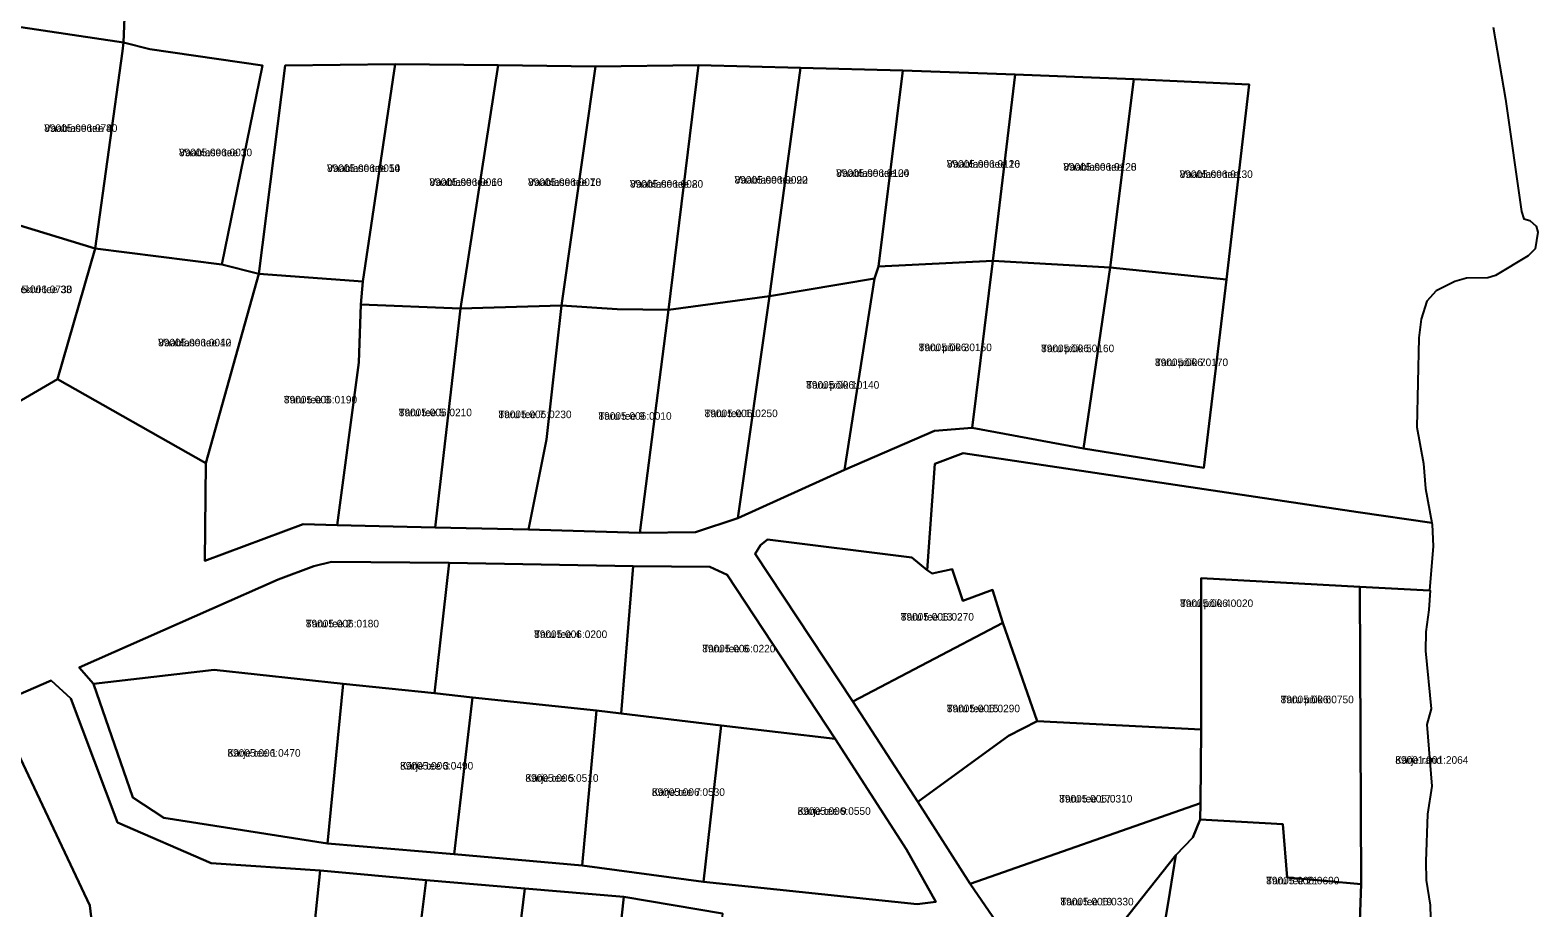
# Model space of a CAD drawing. Extents: x 526849 to 562296, y 6591741 to 6618546.
# Drawn here: x 551338.6 to 551637.5, y 6597493.2 to 6597667.2 of the extents above; entities that cross this region are included whole.
import ezdxf

# ---------------------------------------------------------------- set-up
doc = ezdxf.new("R2010")
doc.units = 0
for name, color, linetype in [('L_AADRESS', 7, 'Continuous'), ('PIIR', 7, 'Continuous'), ('TUNNUS', 7, 'Continuous')]:
    doc.layers.add(name, color=color, linetype=linetype)

msp = doc.modelspace()

# ---------------------------------------------------------------- linework, layer by layer
at = {"layer": 'PIIR'}
for points in [[(550642.16, 6598609.49), (550659.82, 6598605.14), (550668.05, 6598592.24), (550686.56, 6598557.97), (551117.21, 6597760.6), (551147.24, 6597726.55), (551257.76, 6597622.75), (551265.4, 6597615.62), (551270.73, 6597618.95), (551273.1, 6597610.57), (551301.36, 6597574.38), (551331.62, 6597533.44), (551350.49, 6597493.63), (551353.55, 6597467.1), (551357.58, 6597431.51), (551357.52, 6597425.22), (551353.03, 6597392.12), (551349.26, 6597364.37), (551348.43, 6597356.79), (551345.28, 6597327.37), (551348.98, 6597326.82), (551346.35, 6597305.43)], [(551357.49, 6597672.95), (551357.16, 6597664.73), (551330.99, 6597668.6)], [(551334.57, 6597592.44), (551344.03, 6597598.02), (551373.48, 6597581.31), (551373.27, 6597562), (551392.74, 6597569.25), (551399.46, 6597569.08), (551418.95, 6597568.6), (551437.41, 6597568.16), (551459.47, 6597567.55), (551470.54, 6597567.64), (551478.92, 6597570.45), (551500.08, 6597579.99), (551517.93, 6597587.77), (551525.35, 6597588.33), (551547.42, 6597584.23), (551571.32, 6597580.41), (551575.79, 6597617.75), (551580.28, 6597656.43), (551557.42, 6597657.46), (551533.88, 6597658.37), (551511.63, 6597659.14), (551491.36, 6597659.69), (551471.11, 6597660.21), (551450.7, 6597659.99), (551431.4, 6597660.26), (551410.99, 6597660.4), (551389.21, 6597660.14), (551383.98, 6597618.89), (551376.61, 6597620.7), (551384.72, 6597660.18), (551362.33, 6597663.42), (551357.16, 6597664.73), (551357.49, 6597672.95)], [(551628.68, 6597667.76), (551631.08, 6597653.46), (551634.29, 6597631.25), (551634.72, 6597629.76), (551635.92, 6597629.41), (551637.19, 6597628.29), (551637.51, 6597627.1), (551636.95, 6597623.85), (551635.62, 6597622.46), (551629.09, 6597618.53), (551627.59, 6597618.06), (551623.38, 6597617.98), (551621.08, 6597617.34), (551617.35, 6597615.52), (551615.52, 6597613.45), (551614.41, 6597609.88), (551613.93, 6597606.15), (551613.54, 6597588.45), (551614.81, 6597581.3), (551615.23, 6597576.32), (551616.51, 6597569.48), (551601.89, 6597571.61), (551523.57, 6597583.35), (551517.94, 6597581.22), (551516.44, 6597560.16), (551513.4, 6597562.63), (551484.81, 6597566.19), (551483.38, 6597565.06), (551482.37, 6597563.34), (551501.7, 6597534.08), (551514.57, 6597514.19), (551524.95, 6597497.97), (551541.83, 6597473.44), (551565.74, 6597503.64), (551564.57, 6597496.23), (551562.88, 6597486.25)], [(551475.86, 6597492.06), (551456.31, 6597495.37), (551436.72, 6597497.03), (551417.15, 6597498.69), (551396.12, 6597500.57), (551374.5, 6597502.05), (551355.94, 6597510.14), (551346.69, 6597534.7), (551342.79, 6597538.24), (551331.62, 6597533.44)]]:
    msp.add_lwpolyline(points, dxfattribs=at)
for points in [[(551325.71, 6597632.51), (551330.99, 6597668.6), (551357.16, 6597664.73), (551356.92, 6597663), (551351.54, 6597623.87), (551326.14, 6597631.61)], [(551356.92, 6597663), (551357.16, 6597664.73), (551362.33, 6597663.42), (551384.72, 6597660.18), (551376.61, 6597620.7), (551351.54, 6597623.87)], [(551389.21, 6597660.14), (551410.99, 6597660.4), (551404.6, 6597617.34), (551383.98, 6597618.89)], [(551404.6, 6597617.34), (551410.99, 6597660.4), (551431.4, 6597660.26), (551423.93, 6597611.98), (551404.16, 6597612.82)], [(551431.4, 6597660.26), (551450.7, 6597659.99), (551443.98, 6597612.62), (551423.93, 6597611.98)], [(551443.98, 6597612.62), (551450.7, 6597659.99), (551471.11, 6597660.21), (551465.17, 6597611.71), (551454.98, 6597611.85)], [(551471.11, 6597660.21), (551491.36, 6597659.69), (551485.19, 6597614.41), (551465.17, 6597611.71)], [(551491.36, 6597659.69), (551511.63, 6597659.14), (551506.82, 6597620.29), (551505.99, 6597617.97), (551485.19, 6597614.41)], [(551511.63, 6597659.14), (551533.88, 6597658.37), (551529.47, 6597621.43), (551506.82, 6597620.29)], [(551533.88, 6597658.37), (551557.42, 6597657.46), (551552.71, 6597620.1), (551529.47, 6597621.43)], [(551557.42, 6597657.46), (551580.28, 6597656.43), (551575.79, 6597617.75), (551552.71, 6597620.1)], [(551305.83, 6597626.29), (551304.57, 6597629.5), (551313.34, 6597637.65), (551325.71, 6597632.51), (551326.14, 6597631.61), (551351.54, 6597623.87), (551344.03, 6597598.02), (551334.57, 6597592.44), (551328.96, 6597600.64)], [(551351.54, 6597623.87), (551376.61, 6597620.7), (551383.98, 6597618.89), (551373.48, 6597581.31), (551344.03, 6597598.02)], [(551505.99, 6597617.97), (551506.82, 6597620.29), (551529.47, 6597621.43), (551525.35, 6597588.33), (551517.93, 6597587.77), (551500.08, 6597579.99)], [(551529.47, 6597621.43), (551552.71, 6597620.1), (551547.42, 6597584.23), (551525.35, 6597588.33)], [(551373.48, 6597581.31), (551383.98, 6597618.89), (551404.6, 6597617.34), (551404.16, 6597612.82), (551403.8, 6597601.28), (551399.46, 6597569.08), (551392.74, 6597569.25), (551373.27, 6597562)], [(551485.19, 6597614.41), (551505.99, 6597617.97), (551500.08, 6597579.99), (551478.92, 6597570.45)], [(551552.71, 6597620.1), (551575.79, 6597617.75), (551571.32, 6597580.41), (551547.42, 6597584.23)], [(551465.17, 6597611.71), (551485.19, 6597614.41), (551478.92, 6597570.45), (551470.54, 6597567.64), (551459.47, 6597567.55)], [(551403.8, 6597601.28), (551404.16, 6597612.82), (551423.93, 6597611.98), (551418.95, 6597568.6), (551399.46, 6597569.08)], [(551423.93, 6597611.98), (551443.98, 6597612.62), (551440.99, 6597586.05), (551437.41, 6597568.16), (551418.95, 6597568.6)], [(551454.98, 6597611.85), (551465.17, 6597611.71), (551459.47, 6597567.55), (551437.41, 6597568.16), (551440.99, 6597586.05), (551443.98, 6597612.62)], [(551531.47, 6597549.72), (551529.4, 6597556.22), (551523.51, 6597554.02), (551521.42, 6597560.36), (551517.44, 6597559.44), (551516.44, 6597560.16), (551517.94, 6597581.22), (551523.57, 6597583.35), (551601.89, 6597571.61), (551616.51, 6597569.48), (551616.56, 6597569.18), (551616.73, 6597564.91), (551616.06, 6597556.12), (551602.24, 6597556.83), (551570.75, 6597558.51), (551570.78, 6597528.52), (551538.24, 6597530.18)], [(551482.37, 6597563.34), (551483.38, 6597565.06), (551484.81, 6597566.19), (551513.4, 6597562.63), (551516.44, 6597560.16), (551517.44, 6597559.44), (551521.42, 6597560.36), (551523.51, 6597554.02), (551529.4, 6597556.22), (551531.47, 6597549.72), (551501.7, 6597534.08)], [(551387.78, 6597558.3), (551348.35, 6597540.85), (551351.17, 6597537.6), (551359, 6597515.04), (551365.16, 6597511.03), (551397.6, 6597505.97), (551422.67, 6597503.81), (551448.09, 6597501.61), (551472.11, 6597498.38), (551514.46, 6597493.91), (551518.18, 6597494.41), (551512.33, 6597504.77), (551498.21, 6597526.72), (551476.83, 6597559.18), (551473.36, 6597560.79), (551458.19, 6597560.95), (551421.72, 6597561.6), (551398.37, 6597561.81), (551394.88, 6597560.92)], [(551351.17, 6597537.6), (551348.35, 6597540.85), (551387.78, 6597558.3), (551394.88, 6597560.92), (551398.37, 6597561.81), (551421.72, 6597561.6), (551418.8, 6597535.77), (551400.71, 6597537.62), (551375.09, 6597540.34)], [(551418.8, 6597535.77), (551421.72, 6597561.6), (551458.19, 6597560.95), (551455.82, 6597531.75), (551450.92, 6597532.3), (551426.33, 6597534.88)], [(551458.19, 6597560.95), (551473.36, 6597560.79), (551476.83, 6597559.18), (551498.21, 6597526.72), (551475.62, 6597529.35), (551455.82, 6597531.75)], [(551570.61, 6597513.92), (551570.78, 6597528.52), (551570.75, 6597558.51), (551602.24, 6597556.83), (551602.5, 6597497.88), (551587.8, 6597499.23), (551586.96, 6597509.8), (551570.54, 6597510.69)], [(551602.24, 6597556.83), (551616.06, 6597556.12), (551616.16, 6597556.12), (551615.91, 6597552.24), (551615.29, 6597547.89), (551615.23, 6597544.17), (551616.35, 6597532.64), (551615.52, 6597529.55), (551616.47, 6597517.33), (551615.66, 6597511.77), (551615.31, 6597502.38), (551615.34, 6597498.71), (551616.16, 6597493.75), (551616.27, 6597488.59), (551613.07, 6597488.1), (551611.21, 6597487.58), (551602.04, 6597485), (551602.5, 6597497.88)], [(551501.7, 6597534.08), (551531.47, 6597549.72), (551538.24, 6597530.18), (551532.58, 6597527.27), (551514.57, 6597514.19)], [(551397.6, 6597505.97), (551365.16, 6597511.03), (551359, 6597515.04), (551351.17, 6597537.6), (551375.09, 6597540.34), (551400.71, 6597537.62)], [(551350.49, 6597493.63), (551331.62, 6597533.44), (551342.79, 6597538.24), (551346.69, 6597534.7), (551355.94, 6597510.14), (551374.5, 6597502.05), (551396.12, 6597500.57), (551392.38, 6597464.36), (551353.55, 6597467.1)], [(551426.33, 6597534.88), (551422.67, 6597503.81), (551397.6, 6597505.97), (551400.71, 6597537.62), (551418.8, 6597535.77)], [(551450.92, 6597532.3), (551448.09, 6597501.61), (551422.67, 6597503.81), (551426.33, 6597534.88)], [(551455.82, 6597531.75), (551475.62, 6597529.35), (551472.11, 6597498.38), (551448.09, 6597501.61), (551450.92, 6597532.3)], [(551498.21, 6597526.72), (551512.33, 6597504.77), (551518.18, 6597494.41), (551514.46, 6597493.91), (551472.11, 6597498.38), (551475.62, 6597529.35)], [(551570.61, 6597513.92), (551524.95, 6597497.97), (551514.57, 6597514.19), (551532.58, 6597527.27), (551538.24, 6597530.18), (551570.78, 6597528.52)], [(551524.95, 6597497.97), (551570.61, 6597513.92), (551570.54, 6597510.69), (551569.12, 6597507.13), (551565.74, 6597503.64), (551541.83, 6597473.44)], [(551586.96, 6597509.8), (551587.8, 6597499.23), (551602.5, 6597497.88), (551602.04, 6597485), (551588.99, 6597486.15), (551562.88, 6597486.25), (551564.57, 6597496.23), (551565.74, 6597503.64), (551569.12, 6597507.13), (551570.54, 6597510.69)], [(551392.38, 6597464.36), (551396.12, 6597500.57), (551417.15, 6597498.69), (551412.63, 6597462.71), (551393.97, 6597464.14)], [(551412.63, 6597462.71), (551417.15, 6597498.69), (551436.72, 6597497.03), (551432.22, 6597460.17), (551412.91, 6597462.32)], [(551436.72, 6597497.03), (551456.31, 6597495.37), (551452.26, 6597458.44), (551432.22, 6597460.17)], [(551456.31, 6597495.37), (551475.86, 6597492.06), (551471.98, 6597456.26), (551452.26, 6597458.44)]]:
    msp.add_lwpolyline(points, close=True, dxfattribs=at)

# ---------------------------------------------------------------- texts
at = {"layer": 'L_AADRESS'}
for s, p in [('Vaablase tee 8', (551341.43, 6597647)), ('Vaablase tee 10', (551368.13, 6597642.18)), ('Vaablase tee 26', (551520.35, 6597639.9)), ('Vaablase tee 14', (551397.48, 6597639.06)), ('Vaablase tee 22', (551478.27, 6597636.75)), ('Vaablase tee 24', (551498.41, 6597638.09)), ('Vaablase tee 28', (551543.45, 6597639.32)), ('Vaablase tee 30', (551566.5, 6597637.87)), ('Vaablase tee 16', (551417.78, 6597636.3)), ('Vaablase tee 18', (551437.32, 6597636.29)), ('Vaablase tee 20', (551457.54, 6597635.94)), ('Suurekivi tee 33', (551332.47, 6597615.04)), ('Vaablase tee 12', (551364, 6597604.49)), ('Taru põik 3', (551514.77, 6597603.54)), ('Taru põik 5', (551539.03, 6597603.34)), ('Taru põik 7', (551561.61, 6597600.58)), ('Taru põik 1', (551492.46, 6597596.1)), ('Taru tee 3', (551388.94, 6597593.18)), ('Taru tee 5', (551411.7, 6597590.64)), ('Taru tee 7', (551431.46, 6597590.26)), ('Taru tee 9', (551451.29, 6597589.94)), ('Taru tee 11', (551472.33, 6597590.46)), ('Taru tee 13', (551511.22, 6597550.13)), ('Taru põik 4', (551566.58, 6597552.82)), ('Taru tee 2', (551393.28, 6597548.79)), ('Taru tee 4', (551438.53, 6597546.68)), ('Taru tee 6', (551471.87, 6597543.83)), ('Taru põik 6', (551586.52, 6597533.75)), ('Taru tee 15', (551520.35, 6597531.96)), ('Kärje tee 1', (551377.74, 6597523.15)), ('Kärje tee 3', (551411.96, 6597520.6)), ('Kärje rand', (551609.25, 6597521.75)), ('Kärje tee 5', (551436.8, 6597518.18)), ('Kärje tee 7', (551461.86, 6597515.39)), ('Kärje tee 9', (551490.76, 6597511.63)), ('Taru tee 17', (551542.63, 6597514.07)), ('Taru tee 21', (551583.66, 6597497.85)), ('Taru tee 19', (551542.88, 6597493.68))]:
    msp.add_text(s, height=1.5, dxfattribs=at).set_placement(p)
at = {"layer": 'TUNNUS'}
for s, p in [('89005:006:0740', (551341.43, 6597647)), ('89005:006:0030', (551368.13, 6597642.18)), ('89005:006:0110', (551520.35, 6597639.9)), ('89005:006:0050', (551397.48, 6597639.06)), ('89005:006:0090', (551478.27, 6597636.75)), ('89005:006:0100', (551498.41, 6597638.09)), ('89005:006:0120', (551543.45, 6597639.32)), ('89005:006:0130', (551566.5, 6597637.87)), ('89005:006:0060', (551417.78, 6597636.3)), ('89005:006:0070', (551437.32, 6597636.29)), ('89005:006:0080', (551457.54, 6597635.94)), ('89005:006:0730', (551332.47, 6597615.04)), ('89005:006:0040', (551364, 6597604.49)), ('89005:006:0150', (551514.77, 6597603.54)), ('89005:006:0160', (551539.03, 6597603.34)), ('89005:006:0170', (551561.61, 6597600.58)), ('89005:006:0140', (551492.46, 6597596.1)), ('89005:006:0190', (551388.94, 6597593.18)), ('89005:006:0210', (551411.7, 6597590.64)), ('89005:006:0230', (551431.46, 6597590.26)), ('89005:006:0010', (551451.29, 6597589.94)), ('89005:006:0250', (551472.33, 6597590.46)), ('89005:006:0270', (551511.22, 6597550.13)), ('89005:006:0020', (551566.58, 6597552.82)), ('89005:006:0180', (551393.28, 6597548.79)), ('89005:006:0200', (551438.53, 6597546.68)), ('89005:006:0220', (551471.87, 6597543.83)), ('89005:006:0750', (551586.52, 6597533.75)), ('89005:006:0290', (551520.35, 6597531.96)), ('89005:006:0470', (551377.74, 6597523.15)), ('89005:006:0490', (551411.96, 6597520.6)), ('89001:001:2064', (551609.25, 6597521.75)), ('89005:006:0510', (551436.8, 6597518.18)), ('89005:006:0530', (551461.86, 6597515.39)), ('89005:006:0550', (551490.76, 6597511.63)), ('89005:006:0310', (551542.63, 6597514.07)), ('89005:006:0690', (551583.66, 6597497.85)), ('89005:006:0330', (551542.88, 6597493.68))]:
    msp.add_text(s, height=1.5, dxfattribs=at).set_placement(p)

doc.saveas('drawing.dxf')
